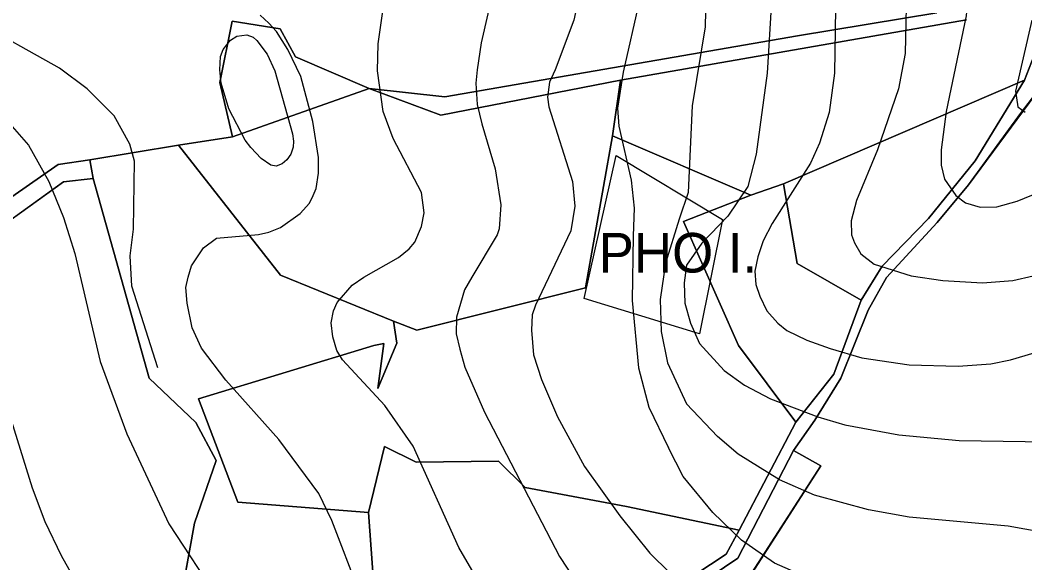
# Model space of a CAD drawing. Extents: x -709418 to -703832, y -1161719 to -1157826.
# Drawn here: x -706225 to -705971, y -1159956.4 to -1159819.1 of the extents above; entities that cross this region are included whole.
import ezdxf

# ---------------------------------------------------------------- set-up
doc = ezdxf.new("R2010")
doc.units = 0
for name, color, linetype in [('102_obvod PÚ', 7, 'Continuous'), ('120_vrstevnice hlavní', 7, 'Continuous'), ('122_vrstevnice základní', 7, 'Continuous'), ('124_vrstevnice doplňková', 7, 'Continuous'), ('206_TTP_KN', 7, 'Continuous'), ('207_lesní pozemek_KN', 7, 'Continuous'), ('210_ostatní plocha_KN', 7, 'Continuous'), ('541_PHO_II. st', 7, 'Continuous'), ('542_PHO_II. st_popis', 7, 'Continuous')]:
    doc.layers.add(name, color=color, linetype=linetype)

msp = doc.modelspace()

# ---------------------------------------------------------------- linework, layer by layer
at = {"layer": '102_obvod PÚ'}
for points in [[(-706132.01, -1160017.23), (-706063.34, -1159989.61), (-706060.53, -1159983.56), (-706051.79, -1159977.72), (-706042.41, -1159962.75), (-706022.6, -1159931.91), (-706029.49, -1159927.99), (-706024.08, -1159920.31), (-706017.53, -1159909.69), (-706010.59, -1159892.53), (-706005.92, -1159884.25), (-705993.15, -1159870.34), (-705985.19, -1159860.82), (-705963.63, -1159831.62)], [(-705963.63, -1159831.62), (-705985.19, -1159860.82), (-705993.15, -1159870.34), (-706005.92, -1159884.25), (-706010.59, -1159892.53), (-706017.53, -1159909.69), (-706024.08, -1159920.31), (-706029.49, -1159927.99), (-706022.6, -1159931.91), (-706042.41, -1159962.75), (-706051.79, -1159977.72), (-706060.53, -1159983.56), (-706063.34, -1159989.61), (-706132.01, -1160017.23)], [(-706184.96, -1159850.81), (-706171.33, -1159848.67), (-706136.72, -1159836.46), (-706118.59, -1159843.16), (-706073.17, -1159834.35), (-706075.21, -1159848.42), (-706082.06, -1159886.88), (-706124.67, -1159897.61), (-706130.61, -1159895.31), (-706159.17, -1159883.63), (-706184.96, -1159850.81)], [(-706184.96, -1159850.81), (-706159.17, -1159883.63), (-706130.61, -1159895.31), (-706124.67, -1159897.61), (-706082.06, -1159886.88), (-706075.21, -1159848.42), (-706073.17, -1159834.35), (-706118.59, -1159843.16), (-706136.72, -1159836.46), (-706171.33, -1159848.67), (-706184.96, -1159850.81)], [(-706057.27, -1159870.06), (-706040.27, -1159863.46), (-706031.99, -1159860.56), (-706028.57, -1159880.71), (-706012.4, -1159889.98), (-706019.3, -1159908.7), (-706028.85, -1159920.87), (-706043.4, -1159901.45), (-706057.27, -1159870.06)], [(-706057.27, -1159870.06), (-706043.4, -1159901.45), (-706028.85, -1159920.87), (-706019.3, -1159908.7), (-706012.4, -1159889.98), (-706028.57, -1159880.71), (-706031.99, -1159860.56), (-706040.27, -1159863.46), (-706057.27, -1159870.06)]]:
    msp.add_lwpolyline(points, dxfattribs=at)
at = {"layer": '120_vrstevnice hlavní'}
for points in [[(-705999.26, -1159770.58), (-705992.26, -1159779.01), (-705988.32, -1159790.83), (-705986.24, -1159801.82), (-705985.44, -1159812.91), (-705985.86, -1159818.04), (-705990.85, -1159842.26), (-705992.13, -1159851.95), (-705992.16, -1159855.82), (-705991.28, -1159859.36), (-705988.43, -1159863.49), (-705985.97, -1159865.34), (-705982.3, -1159866.48), (-705978.03, -1159866.34), (-705972.9, -1159864.92), (-705948.39, -1159854.94)], [(-706068.37, -1159814.05), (-706072.5, -1159832.29), (-706073.93, -1159841.4), (-706073.64, -1159845.96), (-706070.51, -1159859.64), (-706069.72, -1159866.72), (-706069.98, -1159873.75), (-706070.25, -1159890.04), (-706068.67, -1159907.11), (-706066.05, -1159917.09), (-706061.1, -1159927.33)], [(-706231.81, -1159840.69), (-706222.83, -1159850.81), (-706217.7, -1159859.93), (-706214, -1159869.05), (-706211.15, -1159878.17), (-706204.73, -1159905.53), (-706198.04, -1159923.77), (-706187.35, -1159946.56), (-706174.67, -1159965.94), (-706157, -1159987.6), (-706146.46, -1159998.29), (-706111.12, -1160027.5), (-706077.49, -1160058.28), (-706072.79, -1160061.84), (-706062.1, -1160068.54), (-706056.26, -1160071.53), (-706050.7, -1160073.88), (-706043.59, -1160076.13), (-706037.31, -1160077.23), (-706030.32, -1160077.38), (-706012.92, -1160072.49), (-705983.77, -1160064.61), (-705952.64, -1160058.71)], [(-705852.98, -1160024.04), (-705865.58, -1160016.55), (-705883.13, -1160006.13), (-705903.79, -1159991.45), (-705917.61, -1159982.9), (-705931, -1159977.06), (-705940.62, -1159974.07), (-705950.95, -1159971.79), (-705970.9, -1159969.22), (-705990.85, -1159967.65), (-706010.8, -1159964.66), (-706016.38, -1159963.54), (-706022.77, -1159961.53), (-706034.31, -1159956.54), (-706042.58, -1159950.7), (-706049.84, -1159943.72), (-706057.4, -1159934.6), (-706061.1, -1159927.33)]]:
    msp.add_lwpolyline(points, dxfattribs=at)
at = {"layer": '122_vrstevnice základní'}
for points in [[(-706103.14, -1159971.36), (-706114.11, -1159952.55), (-706125.65, -1159926.9), (-706132.78, -1159916.64), (-706143.46, -1159905.1), (-706144.89, -1159902.68), (-706145.89, -1159899.26), (-706146.32, -1159895.7), (-706145.74, -1159892.7), (-706144.83, -1159890.55), (-706141.08, -1159886.16), (-706138.05, -1159884.15), (-706129.36, -1159879.17), (-706126.6, -1159877.01), (-706125.22, -1159875.32), (-706123.51, -1159871.33), (-706122.8, -1159867.91), (-706123.51, -1159862.78), (-706130.64, -1159849.1), (-706133.2, -1159842.26), (-706134.63, -1159832), (-706134.49, -1159825.16), (-706132.06, -1159808.06)], [(-706051.55, -1159808.92), (-706051.84, -1159820.89), (-706055.12, -1159840.83), (-706056.11, -1159862.78), (-706058.39, -1159869.48), (-706061.85, -1159880.59), (-706063.16, -1159889.78), (-706062.9, -1159897.92), (-706061.32, -1159905.8), (-706056.54, -1159916.21)], [(-706000.83, -1159807.78), (-706001.25, -1159827.58), (-706002.96, -1159836.56), (-706008.24, -1159851.95), (-706013.51, -1159864.77), (-706014.93, -1159869.9), (-706014.79, -1159873.47), (-706014.08, -1159875.46), (-706012.46, -1159878.26), (-706009.09, -1159880.88), (-705999.69, -1159883.87), (-705991.71, -1159885.01), (-705981.73, -1159885.58), (-705974.04, -1159885.01), (-705968.91, -1159883.87)], [(-706105.27, -1159811.2), (-706108.41, -1159824.88), (-706109.42, -1159831.75), (-706109.8, -1159835.13), (-706109.42, -1159840.52), (-706108.27, -1159845.39), (-706104.85, -1159856.79), (-706103.42, -1159865.91), (-706103.85, -1159871.9), (-706104.42, -1159873.47), (-706110.83, -1159884.15), (-706112.63, -1159887.41), (-706114.7, -1159894.31), (-706114.77, -1159898.46), (-706113.82, -1159902.39), (-706112.54, -1159906.95), (-706107.55, -1159918.35), (-706088.6, -1159954.83), (-706082.62, -1159963.95)], [(-706018.78, -1159810.63), (-706019.07, -1159832.57), (-706020.49, -1159842.54), (-706022.91, -1159850.24), (-706025.19, -1159855.37), (-706034.88, -1159870.61), (-706037.16, -1159875), (-706038.45, -1159879.02), (-706039.22, -1159882.65), (-706039.02, -1159886.01), (-706038.02, -1159889), (-706036.18, -1159892.69), (-706033.46, -1159895.84), (-706031.18, -1159897.69), (-706026.09, -1159900.08), (-706020.21, -1159902.25), (-706012.23, -1159904.53), (-706000.26, -1159906.38), (-705987.86, -1159906.67), (-705979.59, -1159906.1), (-705974.61, -1159905.1), (-705966.37, -1159902.59)], [(-706303.2, -1159813.62), (-706294.51, -1159822.03), (-706250.48, -1159859.93), (-706244.78, -1159865.49), (-706240.07, -1159871.9), (-706234.94, -1159883.3), (-706227.25, -1159920.35), (-706221.98, -1159937.45), (-706218.7, -1159946), (-706214.57, -1159954.55), (-706206.59, -1159968.79), (-706200.74, -1159977.34), (-706188.96, -1159992.37), (-706182.93, -1159999), (-706109.98, -1160066.97), (-706091.17, -1160085.5), (-706081.56, -1160089.38), (-706061.47, -1160090.96), (-706042.29, -1160091.2)], [(-706035.03, -1159814.33), (-706036.17, -1159832.57), (-706038.87, -1159853.09), (-706041.01, -1159861.21)], [(-706084.33, -1159816.04), (-706085.04, -1159819.18), (-706089.74, -1159831.72), (-706091.19, -1159834.88), (-706091.7, -1159838.64), (-706091.31, -1159841.12), (-706085.33, -1159859.93), (-706084.76, -1159866.2), (-706085.75, -1159872.47), (-706094.73, -1159891.28), (-706095.51, -1159893.69), (-706095.73, -1159897.55), (-706095.16, -1159903.82), (-706093.16, -1159910.09), (-706089.17, -1159919.49), (-706082.33, -1159932.03), (-706073.35, -1159944.57), (-706065.8, -1159953.98), (-706055.69, -1159963.95)], [(-706139.19, -1159963.95), (-706146.17, -1159945.71), (-706149.45, -1159938.87), (-706159.57, -1159925.19), (-706172.96, -1159910.23), (-706179.09, -1159902.11), (-706181.47, -1159896.95), (-706182.79, -1159890.71), (-706183.08, -1159886.78), (-706182.51, -1159884.15), (-706181.65, -1159881.3), (-706178.66, -1159876.74), (-706175.38, -1159874.32), (-706164.74, -1159873.37), (-706162.13, -1159872.75), (-706159.18, -1159871.61), (-706154.15, -1159868.05), (-706151.81, -1159865.47), (-706150.87, -1159863.49), (-706150.16, -1159861.78), (-706149.54, -1159857.85), (-706149.59, -1159853.94), (-706151.02, -1159844.82), (-706154.01, -1159833.43), (-706157.29, -1159826.58), (-706160.14, -1159822.03), (-706162.13, -1159819.89), (-706164.26, -1159817.94)], [(-705969.19, -1159819.18), (-705973.32, -1159837.13), (-705972.75, -1159841.12), (-705970.9, -1159842.4)], [(-706041.01, -1159861.21), (-706046.09, -1159868.77), (-706052.66, -1159875.6), (-706056.54, -1159881.16), (-706057.11, -1159885.58), (-706056.97, -1159890.71), (-706055.54, -1159895.84), (-706053.26, -1159900.97), (-706046.99, -1159907.81), (-706041.86, -1159911.51), (-706035.31, -1159914.93), (-706023.34, -1159919.49), (-706016.5, -1159921.49), (-706002.82, -1159924.05), (-705987.57, -1159925.48), (-705959.79, -1159925.9)], [(-705836.19, -1160013.74), (-705859.76, -1159996.01), (-705875.72, -1159985.75), (-705899.94, -1159972.36), (-705924.16, -1159960.96), (-705938.56, -1159955.4), (-705953.23, -1159951.12), (-705975.18, -1159947.14), (-706000.26, -1159944.85), (-706010.52, -1159943), (-706024.2, -1159939.3), (-706033.03, -1159935.45), (-706043.43, -1159928.9), (-706048.7, -1159924.48), (-706056.54, -1159916.21)]]:
    msp.add_lwpolyline(points, dxfattribs=at)
at = {"layer": '124_vrstevnice doplňková'}
for points in [[(-706190.14, -1159907.1), (-706196.76, -1159886.43), (-706197.18, -1159878.74), (-706196.33, -1159872.04), (-706196.04, -1159854.8), (-706197.25, -1159850.5), (-706201.17, -1159843.4), (-706208.01, -1159836.56), (-706214.99, -1159831.29), (-706236.8, -1159819.18), (-706244.45, -1159814.97)], [(-706174.2, -1159835.12), (-706174.46, -1159831.73), (-706174.33, -1159828.35), (-706173.67, -1159826.58), (-706171.77, -1159824.18), (-706170.24, -1159823.17), (-706167.69, -1159822.88), (-706166.05, -1159823.46), (-706165.12, -1159824.31), (-706162.56, -1159827.73), (-706160.56, -1159832), (-706156.13, -1159847.94), (-706155.87, -1159849.79), (-706155.97, -1159851.29), (-706156.54, -1159853.09), (-706157.57, -1159854.51), (-706158.71, -1159855.51), (-706160.24, -1159856.06), (-706161.61, -1159855.82), (-706164.02, -1159854.18), (-706166.68, -1159851.37), (-706168.11, -1159849.53), (-706172.25, -1159841.55), (-706174.2, -1159835.12)]]:
    msp.add_lwpolyline(points, dxfattribs=at)
at = {"layer": '206_TTP_KN'}
for p, q in [((-705958.4, -1159801.47), (-705971.04, -1159834.3)), ((-706073.17, -1159834.35), (-705985.72, -1159819.11)), ((-706075.21, -1159848.42), (-706073.17, -1159834.35)), ((-705971.04, -1159834.3), (-706031.99, -1159860.56)), ((-706031.99, -1159860.56), (-705971.04, -1159834.3)), ((-705971.04, -1159834.3), (-705983.56, -1159854.77)), ((-706040.27, -1159863.46), (-706075.21, -1159848.42)), ((-706207.37, -1159854.45), (-706184.96, -1159850.81)), ((-706184.96, -1159850.81), (-706159.17, -1159883.63)), ((-706206.51, -1159859.19), (-706207.37, -1159854.45)), ((-705983.56, -1159854.77), (-705995.34, -1159869.31)), ((-706192.38, -1159909.69), (-706206.51, -1159859.19)), ((-706031.99, -1159860.56), (-706040.27, -1159863.46)), ((-706028.57, -1159880.71), (-706031.99, -1159860.56)), ((-705995.34, -1159869.31), (-706007.02, -1159881.35)), ((-706012.4, -1159889.98), (-706028.57, -1159880.71)), ((-706159.17, -1159883.63), (-706130.61, -1159895.31)), ((-706007.02, -1159881.35), (-706012.4, -1159889.98)), ((-706130.61, -1159895.31), (-706129.73, -1159900.89)), ((-706135.57, -1159901.49), (-706179.85, -1159914.93)), ((-706133.06, -1159900.94), (-706135.57, -1159901.49)), ((-706129.73, -1159900.89), (-706134.58, -1159912.35)), ((-706134.58, -1159912.35), (-706133.06, -1159900.94)), ((-706180.56, -1159920.94), (-706192.38, -1159909.69)), ((-706179.85, -1159914.93), (-706169.94, -1159941.08)), ((-706175.39, -1159930.57), (-706180.56, -1159920.94)), ((-706136.89, -1159943.66), (-706132.89, -1159927)), ((-706132.89, -1159927), (-706124.86, -1159930.92)), ((-706043.58, -1159955.26), (-706029.49, -1159927.99)), ((-706029.49, -1159927.99), (-706022.6, -1159931.91)), ((-706180.93, -1159946.41), (-706175.39, -1159930.57)), ((-706124.86, -1159930.92), (-706104.05, -1159930.71)), ((-706104.05, -1159930.71), (-706097.33, -1159937.36)), ((-706022.6, -1159931.91), (-706042.41, -1159962.75)), ((-706097.33, -1159937.36), (-706071.71, -1159942.18)), ((-706169.94, -1159941.08), (-706136.89, -1159943.66)), ((-706071.71, -1159942.18), (-706043.17, -1159948.17)), ((-706136.89, -1159943.66), (-706134.75, -1159973.55)), ((-706134.75, -1159973.55), (-706136.89, -1159943.66)), ((-706184.19, -1159964.56), (-706180.93, -1159946.41)), ((-706043.17, -1159948.17), (-706046.5, -1159954.19)), ((-706046.5, -1159954.19), (-706087.81, -1159981.49)), ((-706127.99, -1160011.89), (-706043.58, -1159955.26))]:
    msp.add_line(p, q, dxfattribs=at)
for points in [[(-705993.23, -1159817.31), (-706028.48, -1159823.09), (-706117.61, -1159838.58), (-706136.72, -1159836.46), (-706155.34, -1159828.47), (-706159.22, -1159821.39), (-706171.35, -1159819.39), (-706174.53, -1159834.93), (-706171.33, -1159848.67), (-706184.96, -1159850.81), (-706207.37, -1159854.45), (-706215.36, -1159855.66), (-706234.41, -1159868.93), (-706265.95, -1159890.91), (-706292.93, -1159911.04), (-706351.32, -1159953.69), (-706374.93, -1159893.92)], [(-706413.58, -1159997.29), (-706367.98, -1159969.18), (-706350.08, -1159962.31), (-706343.41, -1159953.14), (-706214, -1159860.05), (-706206.51, -1159859.19), (-706192.38, -1159909.69), (-706180.56, -1159920.94), (-706175.39, -1159930.57), (-706180.93, -1159946.41), (-706184.19, -1159964.56), (-706196.25, -1159987.17), (-706193.33, -1159995.89), (-706203.49, -1160009.13), (-706223.31, -1160016.31), (-706213.95, -1160037.42), (-706236.24, -1160042.23), (-706254.64, -1160055.47), (-706283.66, -1160063.68), (-706297.39, -1160072.88), (-706316, -1160101.65), (-706356.2, -1160135.9), (-706380.05, -1160156.71), (-706396.05, -1160164.64)]]:
    msp.add_lwpolyline(points, dxfattribs=at)
at = {"layer": '207_lesní pozemek_KN'}
for p, q in [((-705972.08, -1159842.79), (-705963.63, -1159831.62)), ((-706118.59, -1159843.16), (-706073.17, -1159834.35)), ((-706073.17, -1159834.35), (-706075.21, -1159848.42)), ((-706171.33, -1159848.67), (-706136.72, -1159836.46)), ((-706136.72, -1159836.46), (-706118.59, -1159843.16)), ((-705985.19, -1159860.82), (-705972.08, -1159842.79)), ((-706184.96, -1159850.81), (-706171.33, -1159848.67)), ((-706075.21, -1159848.42), (-706082.06, -1159886.88)), ((-706159.17, -1159883.63), (-706184.96, -1159850.81)), ((-706040.27, -1159863.46), (-706031.99, -1159860.56)), ((-706031.99, -1159860.56), (-706028.57, -1159880.71)), ((-705993.15, -1159870.34), (-705985.19, -1159860.82)), ((-706057.27, -1159870.06), (-706040.27, -1159863.46)), ((-706043.4, -1159901.45), (-706057.27, -1159870.06)), ((-706005.92, -1159884.25), (-705993.15, -1159870.34)), ((-706028.57, -1159880.71), (-706012.4, -1159889.98)), ((-706130.61, -1159895.31), (-706159.17, -1159883.63)), ((-706010.59, -1159892.53), (-706005.92, -1159884.25)), ((-706082.06, -1159886.88), (-706124.67, -1159897.61)), ((-706012.4, -1159889.98), (-706019.3, -1159908.7)), ((-706017.53, -1159909.69), (-706010.59, -1159892.53)), ((-706124.67, -1159897.61), (-706130.61, -1159895.31)), ((-706028.85, -1159920.87), (-706043.4, -1159901.45)), ((-706019.3, -1159908.7), (-706028.85, -1159920.87)), ((-706024.08, -1159920.31), (-706017.53, -1159909.69)), ((-706029.49, -1159927.99), (-706024.08, -1159920.31)), ((-706022.6, -1159931.91), (-706029.49, -1159927.99)), ((-706042.41, -1159962.75), (-706022.6, -1159931.91))]:
    msp.add_line(p, q, dxfattribs=at)
at = {"layer": '210_ostatní plocha_KN'}
for p, q in [((-705971.04, -1159834.3), (-705958.4, -1159801.47)), ((-706028.48, -1159823.09), (-705993.23, -1159817.31)), ((-706174.53, -1159834.93), (-706171.35, -1159819.39)), ((-706171.35, -1159819.39), (-706159.22, -1159821.39)), ((-705985.72, -1159819.11), (-706073.17, -1159834.35)), ((-706159.22, -1159821.39), (-706155.34, -1159828.47)), ((-706117.61, -1159838.58), (-706028.48, -1159823.09)), ((-706155.34, -1159828.47), (-706136.72, -1159836.46)), ((-705963.63, -1159831.62), (-705972.08, -1159842.79)), ((-706171.33, -1159848.67), (-706174.53, -1159834.93)), ((-706073.17, -1159834.35), (-706118.59, -1159843.16)), ((-705983.56, -1159854.77), (-705971.04, -1159834.3)), ((-706136.72, -1159836.46), (-706171.33, -1159848.67)), ((-706136.72, -1159836.46), (-706117.61, -1159838.58)), ((-706118.59, -1159843.16), (-706136.72, -1159836.46)), ((-705972.08, -1159842.79), (-705985.19, -1159860.82)), ((-706082.06, -1159886.88), (-706075.21, -1159848.42)), ((-706075.21, -1159848.42), (-706040.27, -1159863.46)), ((-706234.41, -1159868.93), (-706215.36, -1159855.66)), ((-706215.36, -1159855.66), (-706207.37, -1159854.45)), ((-706207.37, -1159854.45), (-706206.51, -1159859.19)), ((-705995.34, -1159869.31), (-705983.56, -1159854.77)), ((-706214, -1159860.05), (-706343.41, -1159953.14)), ((-706206.51, -1159859.19), (-706214, -1159860.05)), ((-705985.19, -1159860.82), (-705993.15, -1159870.34)), ((-706040.27, -1159863.46), (-706057.27, -1159870.06)), ((-706057.27, -1159870.06), (-706043.4, -1159901.45)), ((-706007.02, -1159881.35), (-705995.34, -1159869.31)), ((-705993.15, -1159870.34), (-706005.92, -1159884.25)), ((-706012.4, -1159889.98), (-706007.02, -1159881.35)), ((-706005.92, -1159884.25), (-706010.59, -1159892.53)), ((-706124.67, -1159897.61), (-706082.06, -1159886.88)), ((-706019.3, -1159908.7), (-706012.4, -1159889.98)), ((-706010.59, -1159892.53), (-706017.53, -1159909.69)), ((-706129.73, -1159900.89), (-706130.61, -1159895.31)), ((-706130.61, -1159895.31), (-706124.67, -1159897.61)), ((-706179.85, -1159914.93), (-706135.57, -1159901.49)), ((-706135.57, -1159901.49), (-706133.06, -1159900.94)), ((-706134.58, -1159912.35), (-706129.73, -1159900.89)), ((-706133.06, -1159900.94), (-706134.58, -1159912.35)), ((-706043.4, -1159901.45), (-706028.85, -1159920.87)), ((-706028.85, -1159920.87), (-706019.3, -1159908.7)), ((-706017.53, -1159909.69), (-706024.08, -1159920.31)), ((-706169.94, -1159941.08), (-706179.85, -1159914.93)), ((-706028.85, -1159920.87), (-706043.17, -1159948.17)), ((-706043.17, -1159948.17), (-706028.85, -1159920.87)), ((-706024.08, -1159920.31), (-706029.49, -1159927.99)), ((-706132.89, -1159927), (-706136.89, -1159943.66)), ((-706124.86, -1159930.92), (-706132.89, -1159927)), ((-706029.49, -1159927.99), (-706043.58, -1159955.26)), ((-706104.05, -1159930.71), (-706124.86, -1159930.92)), ((-706097.33, -1159937.36), (-706104.05, -1159930.71)), ((-706071.71, -1159942.18), (-706097.33, -1159937.36)), ((-706136.89, -1159943.66), (-706169.94, -1159941.08)), ((-706043.17, -1159948.17), (-706071.71, -1159942.18)), ((-706046.5, -1159954.19), (-706043.17, -1159948.17)), ((-706087.81, -1159981.49), (-706046.5, -1159954.19)), ((-706043.58, -1159955.26), (-706127.99, -1160011.89))]:
    msp.add_line(p, q, dxfattribs=at)
at = {"layer": '541_PHO_II. st'}
msp.add_lwpolyline([(-706053.23, -1159898.49), (-706082.43, -1159889.53), (-706074.34, -1159853.4), (-706047.38, -1159869.58)], close=True, dxfattribs=at)

# ---------------------------------------------------------------- texts
at = {"layer": '542_PHO_II. st_popis'}
msp.add_text('PHO I. ', height=10, dxfattribs=at).set_placement((-706078.74, -1159882.99))

doc.saveas('drawing.dxf')
